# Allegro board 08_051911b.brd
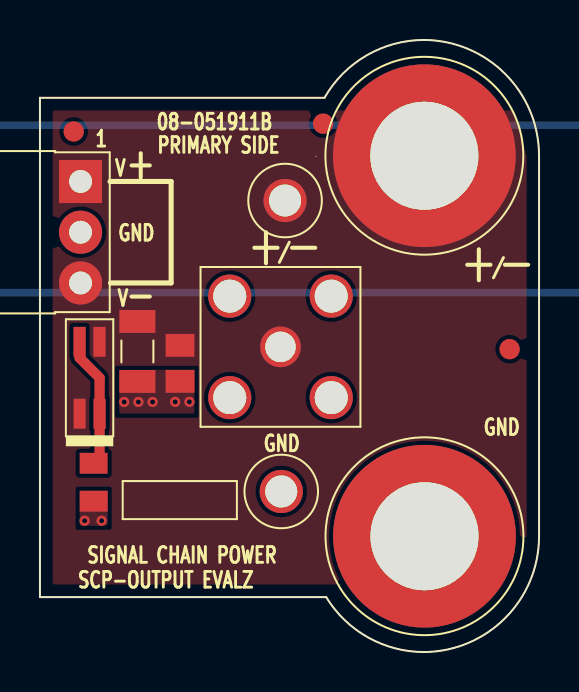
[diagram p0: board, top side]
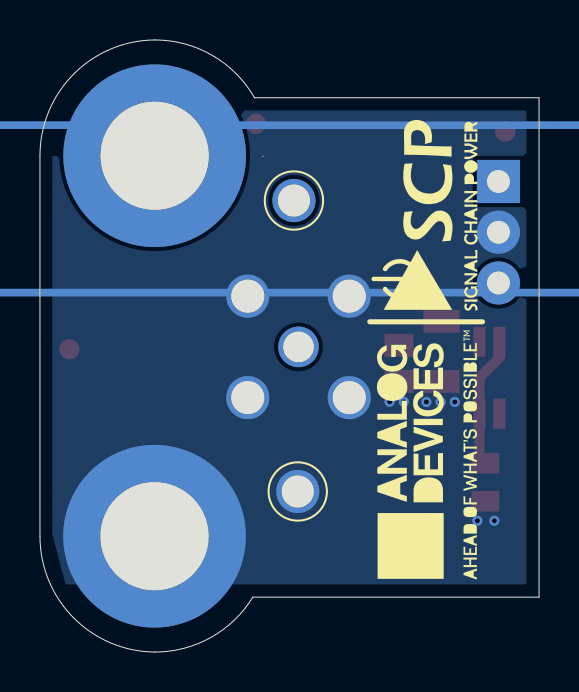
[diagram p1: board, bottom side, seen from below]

Outline 24.98 x 30.65 mm; copper layers: TOP, L2_GND, L3_SIG, BOTTOM. Coordinates in mm from the lower left corner of the outline.
Outline path: 13.82,24.82 13.82,24.82 ; 0,27.75 0,2.75 14.33,2.75 arc(16.42,0.73) 19.23,0 arc(23.3,1.71) 24.98,5.8 24.98,24.85 arc(23.3,28.93) 19.23,30.65 arc(16.34,29.87) 14.24,27.75 0,27.75

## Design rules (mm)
constraint set DEFAULT: min track width 0.203

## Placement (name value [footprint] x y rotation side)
C1  TBD1206  [C1206]  4.88 15.05 270 top
C2  TBD0805  [C0805]  7.01 14.46 90 top
J1  575-4  [CNBANANAD312LD203]  19.24 24.85 0 top
J2  575-4  [CNBANANAD312LD203]  19.25 5.8 0 top
LED1  LTST-C235KGKRKT  [LED1206_4P]  2.48 13.73 90 top
NOREF  -  [unnamed]  1.69 26.06 0 top
NOREF#2  -  [#2]  2.03 23.56 0 top
NOREF#3  -  [#2]  2.03 23.56 0 top
NOREF#4  -  [#2]  0 2.75 0 top
NOREF#5  -  [#2]  24.99 0.22 90 top
NOREF#6  -  [#2]  0 2.75 0 top
NOREF#7  -  [#2]  25.04 30.42 180 top
NOREF#8  -  [#2]  92.2 45.78 0 top
NOREF#9  -  [#2]  0 27.75 270 top
NOREF#10  -  [#2]  -36.32 108.52 0 top
NOREF#11  -  [#2]  11.32 42.04 0 top
NOREF#12  -  [unnamed]  23.51 15.16 0 top
NOREF#13  -  [#2]  -19.05 288.86 0 top
NOREF#14  -  [#2]  -69.98 -51.37 0 top
NOREF#15  -  [#2]  23.97 28.12 0 top
NOREF#16  -  [unnamed]  14.17 26.45 0 top
NOREF#17  -  [#2]  0 2.75 90 top
NOREF#18  -  [#2]  -59.69 350.96 0 top
NOREF#19  -  [#2]  5.73 21.89 90 bottom
NOREF#20  -  [#2]  5.58 9.58 90 bottom
P1  PBC03SBAN  [CNTHMHDRRA1X3L300W100H145]  2.03 23.56 270 top
R1  TBD0805  [R0805]  2.69 8.5 270 top
SMA1  5-1814832-1  [CNTYCO1814832]  12.04 15.28 0 top
TP1  RED  [CNKEY5XXXTP]  12.27 22.61 0 top
TP2  BLK  [CNKEY5XXXTP]  12.08 8.04 0 top

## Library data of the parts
C1 = CAP: User Part Number: UPN; alternate symbols: (); part number: CAP_SM-TBD1206,TBD1206,TBD1206,E000384,C1206
C2 = CAP: User Part Number: UPN; alternate symbols: (); part number: CAP_SM-TBD0805,TBD0805,TBD0805,E000383,C0805
J1 J2 = CNTP1P: Tolerance: N/A; User Part Number: UPN; alternate symbols: (); part number: CNTP1P_TH-575-4,E012555,CNBANANAD312LD203; tolerance: N/A
LED1 = DIOLED_4P_V21: User Part Number: UPN; Tolerance: N/A; alternate symbols: (LED1206_4P_67BRDTHK); part number: DIOLED_4P_V21_SM-LTST-C235KGKRKT,2V,N/A,E034174,LED1206_4P; tolerance: N/A
P1 = CN3P: Tolerance: N/A; User Part Number: UPN; alternate symbols: (CNTHMHDRRA1X3L300W100H145_SCP); part number: CN3P_TH-PBC03SBAN,E034137,CNTHMHDRRA1X3L300W100H145; tolerance: N/A
R1 = RES: User Part Number: UPN; alternate symbols: (R0805L); part number: RES_SM-TBD0805,E004051,TBD0805,TBD0805,R0805
SMA1 = CNBNC5P: Tolerance: N/A; User Part Number: UPN; alternate symbols: (); part number: CNBNC5P_TH-5-1814832-1,E010606,CNTYCO1814832; tolerance: N/A
TP1 = CNTP1P: Tolerance: N/A; User Part Number: UPN; alternate symbols: (); part number: CNTP1P_TH-RED,E023025,CNKEY5XXXTP; tolerance: N/A
TP2 = CNTP1P: Tolerance: N/A; User Part Number: UPN; alternate symbols: (); part number: CNTP1P_TH-BLK,E022843,CNKEY5XXXTP; tolerance: N/A

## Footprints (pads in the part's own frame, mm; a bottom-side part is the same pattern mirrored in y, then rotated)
C0805
  rect 1.143x1.448 smd: 1(-0.9,0) 2(0.9,0)
C1206
  rect 1.143x1.803 smd: 1(-1.5,0) 2(1.5,0)
CNBANANAD312LD203
  round 9.144 hole 5.41: 1(0,0)
CNKEY5XXXTP
  round 2.159 hole 1.6: 1(0,0)
CNTHMHDRRA1X3L300W100H145
  rect 2.159x2.159 hole 1.143: 1(0,0)
  round 2.159 hole 1.143: 2(2.54,0) 3(5.08,0)
CNTYCO1814832
  round 2.032 hole 1.524: 1(0,0)
  round 2.159 hole 1.651: 2(-2.54,2.54) 3(2.54,2.54) 4(2.54,-2.54) 5(-2.54,-2.54)
LED1206_4P
  rect 1.499x0.61 smd: 1(-1.8,-0.5) 2(1.8,-0.5) 3(1.8,0.5) 4(-1.8,0.5)
R0805
  rect 1.041x1.397 smd: 1(-0.95,0) 2(0.95,0)
unnamed
  round 1.016 smd: (0,0)

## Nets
AGND: C1.2(N2) C2.1 J2.1(N1) P1.2 R1.2(N2) SMA1.2 SMA1.3 SMA1.4 SMA1.5(SH4) TP2.1(N1)
UNNAMED_2_CAP_I8_N1: C1.1 C2.2(N2) J1.1(N1) LED1.2 LED1.4(C2) P1.1 P1.3(N3) SMA1.1 TP1.1(N1)
UNNAMED_2_DIOLED4PV21_I11_A2: LED1.1 LED1.3 R1.1

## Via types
v1: diameter 0.508, hole 0.254, TOP to BOTTOM, 7 vias

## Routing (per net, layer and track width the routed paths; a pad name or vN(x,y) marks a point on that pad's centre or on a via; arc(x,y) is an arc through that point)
AGND: length 0
  vias: v1(2.24,6.58) v1(3.09,6.58) v1(4.22,12.52) v1(4.93,12.52) v1(5.64,12.52) v1(6.77,12.53) v1(7.48,12.53)
UNNAMED_2_DIOLED4PV21_I11_A2: length 6.6
  TOP w0.508: LED1.3 1.98,14.73 2.98,13.73 LED1.1 2.98,9.75 R1.1

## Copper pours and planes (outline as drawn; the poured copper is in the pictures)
AGND on TOP: 1.99,8.07 1.99,6.32 3.39,6.32 3.39,8.07
AGND on TOP: 7.73,14.13 7.73,11.93 3.96,11.93 3.96,14.13
AGND on BOTTOM: 0.64,3.38 0.64,27.11 24.36,27.11 24.36,5.91 23.7,3.38 ; 1 cut-out
UNNAMED_2_CAP_I8_N1 on TOP: 0.64,3.38 0.64,27.11 23.75,27.11 24.36,24.78 24.36,3.38 ; 1 cut-out

Small or netless copper shapes (teardrops, artwork), in the pictures only: 1 on L2_GND, 1 on L3_SIG

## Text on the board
Ref Des/Silkscreen Top: V | GND | SCP-OUTPUT EVALZ | SIGNAL CHAIN POWER | 08-051911B | PRIMARY SIDE | / | + | - | +-
PAGE_OUTLINE: 04DEC18 | B | AS PER ECR-086431 | 08MAY19 | J.VIERNES
DIMENSION: 2X | (REF) | SEE FAB NOTE 15 | DIA MAX
User.11: VIEW FROM PRIMARY SIDE
User.15: 15.    THRU VIAS FILLED WITH SOLDERMASK. | .0028" | .0014" | .0035"
User.17: L2 GND | 08-      -07
User.18: L3 SIG | 08-      -08
User.45: FIGURE | SIZE | 10.0 | 45.0 | 60.0 | 63.0 | 65.0 | 213.0 | PLATED | FINISHED HOLES IN MILS | ALL UNITS ARE IN MILS | QTY | 7 | 3 | 1 | 2 | 4 | TOLERANCE/NOTES
